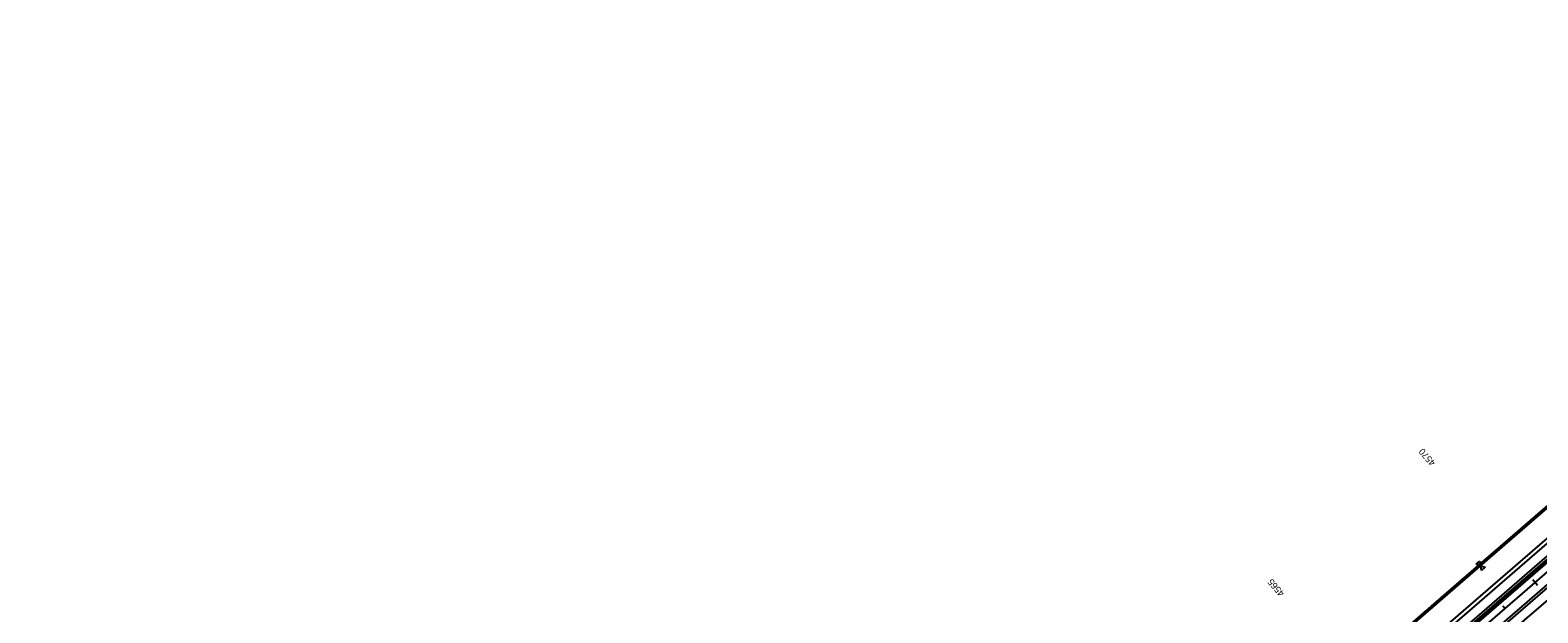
# Model space of a CAD drawing. Extents: x 192699 to 285914, y 194342 to 233219.
# Drawn here: x 202201 to 205979, y 205094 to 206554 of the extents above; entities that cross this region are included whole.
import ezdxf

# ---------------------------------------------------------------- set-up
doc = ezdxf.new("R2010")
doc.units = 0
for name, color, linetype in [('CENT LINE', 7, 'Continuous'), ('CONCRETE', 7, 'Continuous'), ('R-W - CofA', 7, 'Continuous'), ('ROAD', 7, 'Continuous'), ('SHOULDER', 7, 'Continuous'), ('STATIONING1', 7, 'Continuous'), ('WRSF', 7, 'Continuous')]:
    doc.layers.add(name, color=color, linetype=linetype)

msp = doc.modelspace()

# ---------------------------------------------------------------- linework, layer by layer
at = {"layer": 'CENT LINE'}
msp.add_line((198833.2, 198989.9), (207514.6, 206505.5), dxfattribs=at)
at = {"layer": 'CONCRETE'}
for p, q in [((203079, 202694.6), (207308.1, 206355.8)), ((203081.6, 202691.6), (207310.6, 206352.7))]:
    msp.add_line(p, q, dxfattribs=at)
at = {"layer": 'R-W - CofA'}
for p, q in [((205824.9, 205216.4), (205834, 205224.2)), ((205836.2, 205212.5), (205824.9, 205216.4)), ((205834, 205224.2), (205836.2, 205212.5)), ((205838.5, 205200.8), (205836.2, 205212.5)), ((205836.2, 205212.5), (205847.5, 205208.6)), ((205847.5, 205208.6), (205838.5, 205200.8))]:
    msp.add_line(p, q, dxfattribs=at)
for points in [[(203774, 203432.6), (206042.1, 205396.1), (206259.1, 205603.8), (207302.5, 206507.1)], [(205840.7, 205216.4), (206044.9, 205393.1), (206101.1, 205447)], [(205838.1, 205219.5), (205959, 205324.2)], [(205962.9, 205327.5), (205967.6, 205331.6)], [(205971.5, 205334.9), (205976.1, 205339)], [(205573.3, 204984.9), (205840.7, 205216.4)], [(205712.6, 205110.9), (205838.1, 205219.5)], [(205695.5, 205096), (205700.2, 205100.1)], [(205704.1, 205103.5), (205708.7, 205107.5)]]:
    msp.add_lwpolyline(points, dxfattribs=at)
at = {"layer": 'ROAD'}
for p, q in [((198797.8, 199030.7), (207479.2, 206546.3)), ((198813.5, 199012.5), (207494.9, 206528.2)), ((198852.8, 198967.2), (207534.2, 206482.8)), ((198868.5, 198949), (207549.9, 206464.7))]:
    msp.add_line(p, q, dxfattribs=at)
at = {"layer": 'SHOULDER'}
for p, q in [((203018.9, 202698.1), (207472.7, 206553.9)), ((203077.6, 202696.1), (207498.9, 206523.7)), ((203109.1, 202659.8), (207530.3, 206487.4))]:
    msp.add_line(p, q, dxfattribs=at)
at = {"layer": 'STATIONING1'}
for points in [[(205966.9, 205177.5), (205978.6, 205163.9)], [(205891.3, 205112.1), (205897.1, 205105.3)]]:
    msp.add_lwpolyline(points, dxfattribs=at)
at = {"layer": 'WRSF'}
msp.add_line((203046.3, 202663.7), (207309.3, 206354.3), dxfattribs=at)

# ---------------------------------------------------------------- texts
at = {"layer": 'STATIONING1'}
for s, p in [('4570', (205723.9, 205470.8)), ('4565', (205345.4, 205144))]:
    msp.add_text(s, height=16.5, rotation=130.8833, dxfattribs=at).set_placement(p)

doc.saveas('drawing.dxf')
